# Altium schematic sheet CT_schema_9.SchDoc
size 281 x 153 mm
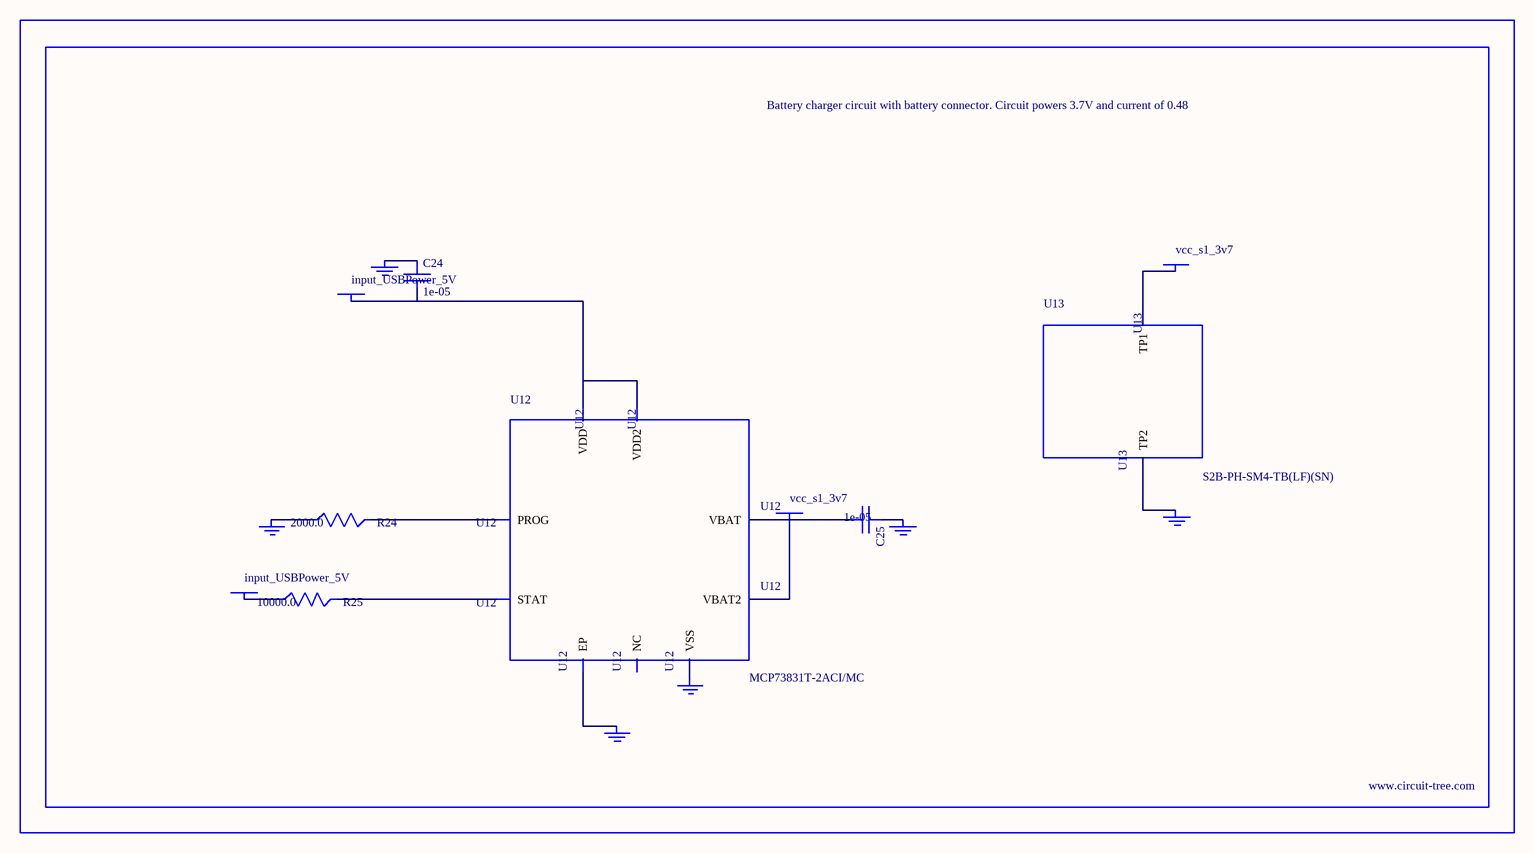
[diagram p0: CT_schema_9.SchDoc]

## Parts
BORDER8  (no value)
C24  1e-05  [C1206]
C25  1e-05  [C1206]
GND_INSTANCE_8_0  (no value)
GND_INSTANCE_8_1  (no value)
GND_INSTANCE_8_2  (no value)
GND_INSTANCE_8_3  (no value)
GND_INSTANCE_8_4  (no value)
GND_INSTANCE_8_5  (no value)
POWER_INSTANCE_8_0  input_USBPower_5V
POWER_INSTANCE_8_1  input_USBPower_5V
POWER_INSTANCE_8_2  vcc_s1_3v7
POWER_INSTANCE_8_3  vcc_s1_3v7
R24  2000.0  [R0603]
R25  10000.0  [R0603]
U12  MCP73831T-2ACI/MC  [DFN8_2X3MC]
U13  S2B-PH-SM4-TB(LF)(SN)  [JST-2-SMD]

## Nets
NetC24_1: C24.1 GND_INSTANCE_8_0.0(GND)
NetC24_2: C24.2 POWER_INSTANCE_8_0.0(PWR) U12.1(VDD) U12.2(VDD2)
NetC25_1: C25.1 GND_INSTANCE_8_1.0(GND)
NetC25_2: C25.2 POWER_INSTANCE_8_2.0(PWR) U12.3(VBAT) U12.4(VBAT2)
NetGND_INSTANCE_8_2_0: GND_INSTANCE_8_2.0(GND) R24.1
NetGND_INSTANCE_8_3_0: GND_INSTANCE_8_3.0(GND) U12.9(EP)
NetGND_INSTANCE_8_4_0: GND_INSTANCE_8_4.0(GND) U12.6(VSS)
NetGND_INSTANCE_8_5_0: GND_INSTANCE_8_5.0(GND) U13.2(TP2)
NetPOWER_INSTANCE_8_1_0: POWER_INSTANCE_8_1.0(PWR) R25.1
NetPOWER_INSTANCE_8_3_0: POWER_INSTANCE_8_3.0(PWR) U13.1(TP1)
NetR24_2: R24.2 U12.8(PROG)
NetR25_2: R25.2 U12.5(STAT)

Not connected (* = marked no-connect by the designer): U12 7(NC)

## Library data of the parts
BORDER8 = BORDER_PAGE8
C24 C25 = C1206C106K3RACTU
GND_INSTANCE_8_0-GND_INSTANCE_8_5 = GND
POWER_INSTANCE_8_0-POWER_INSTANCE_8_3 = PWR
R24 = RC0603JR-072KL
R25 = RC0603JR-0710KL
